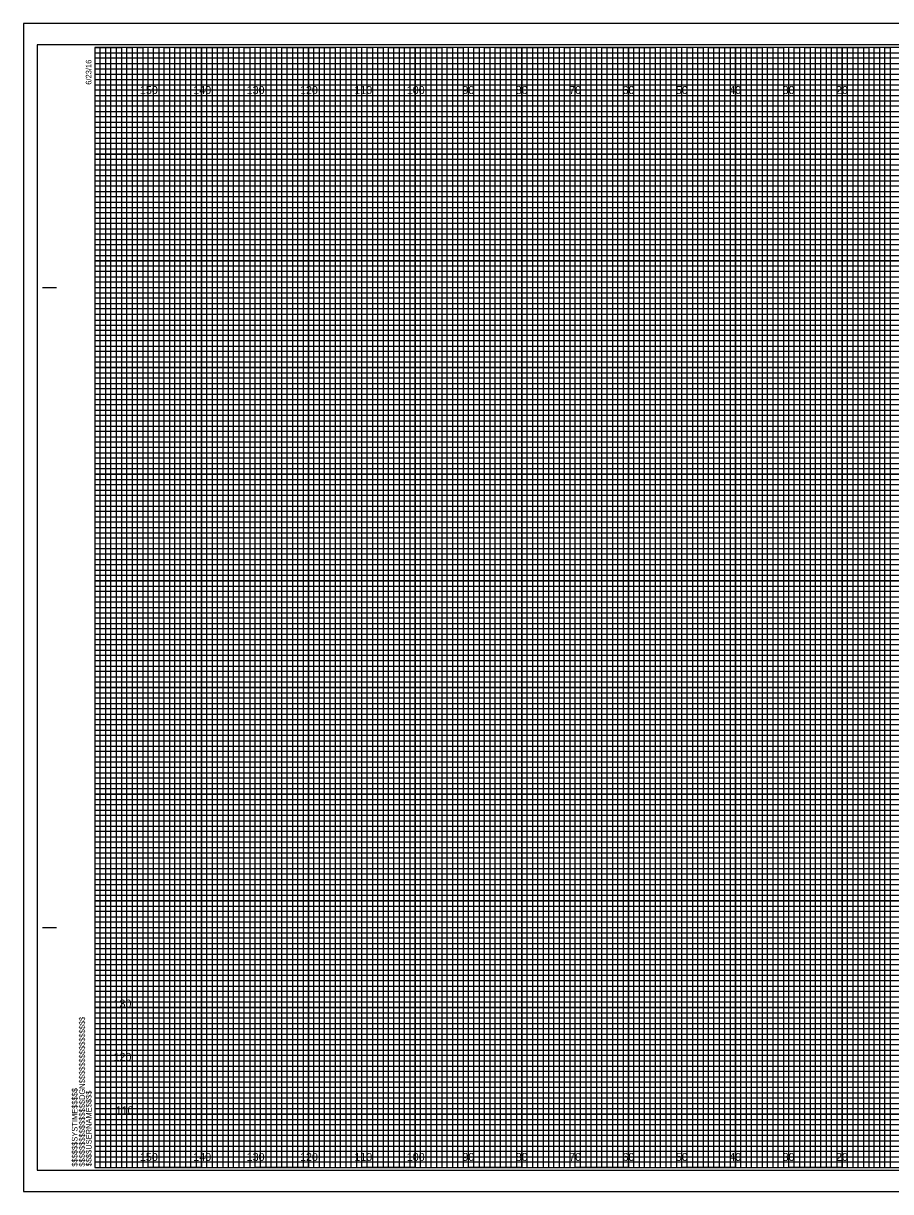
# Model space of a CAD drawing. Extents: x -13 to 323, y -5 to 434.
# Drawn here: x -13.4 to 149.1, y 215.5 to 434.5 of the extents above; entities that cross this region are included whole.
import ezdxf

# ---------------------------------------------------------------- set-up
doc = ezdxf.new("R2010")
doc.units = 0
for name, color, linetype in [('Exist CMT Pavement', 7, 'Continuous'), ('Exist Cross Section Cell', 7, 'Continuous'), ('Exist XS Center Line Elevation Label', 7, 'Continuous'), ('Exist XS Ground Line', 7, 'Continuous'), ('Prop CMT Concrete Structures', 7, 'Continuous'), ('Prop CMT Pvmt Course 1 Wedge', 7, 'Continuous'), ('Prop CMT Pvmt Course 2', 7, 'Continuous'), ('Prop CMT Pvmt Course 2 Wedge', 7, 'Continuous'), ('Prop CMT Pvmt Course 3', 7, 'Continuous'), ('Prop CMT Pvmt Course 3 Wedge', 7, 'Continuous'), ('Scratch_Level_0', 7, 'Continuous')]:
    doc.layers.add(name, color=color, linetype=linetype)

msp = doc.modelspace()

# ---------------------------------------------------------------- linework, layer by layer
at = {"layer": 'Exist XS Center Line Elevation Label'}
for points in [[(0, 430), (5, 430), (5, 220), (15, 220), (15, 430), (25, 430), (25, 220), (35, 220), (35, 430), (45, 430), (45, 220), (55, 220), (55, 430), (65, 430), (65, 220), (75, 220), (75, 430), (85, 430), (85, 220), (95, 220), (95, 430), (105, 430), (105, 220), (115, 220), (115, 430), (125, 430), (125, 220), (135, 220), (135, 430), (145, 430), (145, 220), (155, 220)], [(0, 425), (275, 425)], [(0, 405), (320, 405), (320, 415), (0, 415)], [(0, 385), (320, 385), (320, 395), (0, 395)], [(0, 365), (320, 365), (320, 375), (0, 375)], [(0, 345), (320, 345), (320, 355), (0, 355)], [(0, 325), (320, 325), (320, 335), (0, 335)], [(0, 305), (320, 305), (320, 315), (0, 315)], [(0, 285), (320, 285), (320, 295), (0, 295)], [(0, 265), (320, 265), (320, 275), (0, 275)], [(0, 245), (320, 245), (320, 255), (0, 255)], [(0, 225), (320, 225), (320, 235), (0, 235)]]:
    msp.add_lwpolyline(points, dxfattribs=at)
at = {"layer": 'Exist XS Ground Line'}
for p, q in [((10, 430), (0, 430)), ((10, 220), (10, 430)), ((30, 430), (20, 430)), ((20, 430), (20, 220)), ((30, 220), (30, 430)), ((50, 430), (40, 430)), ((40, 430), (40, 220)), ((50, 220), (50, 430)), ((70, 430), (60, 430)), ((60, 430), (60, 220)), ((70, 220), (70, 430)), ((90, 430), (80, 430)), ((80, 430), (80, 220)), ((90, 220), (90, 430)), ((110, 430), (100, 430)), ((100, 430), (100, 220)), ((110, 220), (110, 430)), ((130, 430), (120, 430)), ((120, 430), (120, 220)), ((130, 220), (130, 430)), ((150, 430), (140, 430)), ((140, 430), (140, 220)), ((20, 220), (10, 220)), ((40, 220), (30, 220)), ((60, 220), (50, 220)), ((80, 220), (70, 220)), ((100, 220), (90, 220)), ((120, 220), (110, 220)), ((140, 220), (130, 220))]:
    msp.add_line(p, q, dxfattribs=at)
for points in [[(0, 420), (320, 420), (320, 410), (0, 410)], [(0, 400), (320, 400), (320, 390), (0, 390)], [(0, 380), (320, 380), (320, 370), (0, 370)], [(0, 360), (320, 360), (320, 350), (0, 350)], [(0, 340), (320, 340), (320, 330), (0, 330)], [(0, 320), (320, 320), (320, 310), (0, 310)], [(0, 300), (320, 300), (320, 290), (0, 290)], [(0, 280), (320, 280), (320, 270), (0, 270)], [(0, 260), (320, 260), (320, 250), (0, 250)], [(0, 240), (320, 240), (320, 230), (0, 230)]]:
    msp.add_lwpolyline(points, dxfattribs=at)
at = {"layer": 'Prop CMT Concrete Structures'}
for p, q in [((323.3, 434.5), (-13.4, 434.5)), ((-13.4, 434.5), (-13.4, 215.5)), ((-13.4, 215.5), (323.3, 215.5))]:
    msp.add_line(p, q, dxfattribs=at)
at = {"layer": 'Prop CMT Pvmt Course 1 Wedge'}
msp.add_lwpolyline([(-13.4, 215.5), (323.3, 215.5), (323.3, 434.5), (-13.4, 434.5)], close=True, dxfattribs=at)
at = {"layer": 'Prop CMT Pvmt Course 2'}
for p, q in [((-9.8, 385), (-7.3, 385)), ((-9.7, 385), (-7.2, 385)), ((-9.8, 265), (-7.3, 265)), ((-9.7, 265), (-7.2, 265)), ((0, 220), (0, 220)), ((0, 220), (0, 220)), ((0, 220), (0, 220)), ((0, 220), (0, 220)), ((0, 220), (0, 220)), ((0, 220), (0, 220)), ((0, 220), (0, 220))]:
    msp.add_line(p, q, dxfattribs=at)
msp.add_lwpolyline([(320, 430), (0, 430), (0, 220), (320, 220)], close=True, dxfattribs=at)
at = {"layer": 'Prop CMT Pvmt Course 2 Wedge'}
msp.add_lwpolyline([(-10.8, 219.5), (322.4, 219.5), (322.4, 430.5), (-10.8, 430.5)], close=True, dxfattribs=at)
at = {"layer": 'Prop CMT Pvmt Course 3'}
for points in [[(0, 220), (1, 220), (1, 430), (2, 430), (2, 220)], [(2, 220), (3, 220), (3, 430), (4, 430), (4, 220)], [(5, 220), (6, 220), (6, 430), (7, 430), (7, 220)], [(7, 220), (8, 220), (8, 430), (9, 430), (9, 220)], [(10, 220), (11, 220), (11, 430), (12, 430), (12, 220)], [(12, 220), (13, 220), (13, 430), (14, 430), (14, 220)], [(15, 220), (16, 220), (16, 430), (17, 430), (17, 220)], [(17, 220), (18, 220), (18, 430), (19, 430), (19, 220)], [(20, 220), (21, 220), (21, 430), (22, 430), (22, 220)], [(22, 220), (23, 220), (23, 430), (24, 430), (24, 220)], [(25, 220), (26, 220), (26, 430), (27, 430), (27, 220)], [(27, 220), (28, 220), (28, 430), (29, 430), (29, 220)], [(30, 220), (31, 220), (31, 430), (32, 430), (32, 220)], [(32, 220), (33, 220), (33, 430), (34, 430), (34, 220)], [(35, 220), (36, 220), (36, 430), (37, 430), (37, 220)], [(37, 220), (38, 220), (38, 430), (39, 430), (39, 220)], [(40, 220), (41, 220), (41, 430), (42, 430), (42, 220)], [(42, 220), (43, 220), (43, 430), (44, 430), (44, 220)], [(45, 220), (46, 220), (46, 430), (47, 430), (47, 220)], [(47, 220), (48, 220), (48, 430), (49, 430), (49, 220)], [(50, 220), (51, 220), (51, 430), (52, 430), (52, 220)], [(52, 220), (53, 220), (53, 430), (54, 430), (54, 220)], [(55, 220), (56, 220), (56, 430), (57, 430), (57, 220)], [(57, 220), (58, 220), (58, 430), (59, 430), (59, 220)], [(60, 220), (61, 220), (61, 430), (62, 430), (62, 220)], [(62, 220), (63, 220), (63, 430), (64, 430), (64, 220)], [(65, 220), (66, 220), (66, 430), (67, 430), (67, 220)], [(67, 220), (68, 220), (68, 430), (69, 430), (69, 220)], [(70, 220), (71, 220), (71, 430), (72, 430), (72, 220)], [(72, 220), (73, 220), (73, 430), (74, 430), (74, 220)], [(75, 220), (76, 220), (76, 430), (77, 430), (77, 220)], [(77, 220), (78, 220), (78, 430), (79, 430), (79, 220)], [(80, 220), (81, 220), (81, 430), (82, 430), (82, 220)], [(82, 220), (83, 220), (83, 430), (84, 430), (84, 220)], [(85, 220), (86, 220), (86, 430), (87, 430), (87, 220)], [(87, 220), (88, 220), (88, 430), (89, 430), (89, 220)], [(90, 220), (91, 220), (91, 430), (92, 430), (92, 220)], [(92, 220), (93, 220), (93, 430), (94, 430), (94, 220)], [(95, 220), (96, 220), (96, 430), (97, 430), (97, 220)], [(97, 220), (98, 220), (98, 430), (99, 430), (99, 220)], [(100, 220), (101, 220), (101, 430), (102, 430), (102, 220)], [(102, 220), (103, 220), (103, 430), (104, 430), (104, 220)], [(105, 220), (106, 220), (106, 430), (107, 430), (107, 220)], [(107, 220), (108, 220), (108, 430), (109, 430), (109, 220)], [(110, 220), (111, 220), (111, 430), (112, 430), (112, 220)], [(112, 220), (113, 220), (113, 430), (114, 430), (114, 220)], [(115, 220), (116, 220), (116, 430), (117, 430), (117, 220)], [(117, 220), (118, 220), (118, 430), (119, 430), (119, 220)], [(120, 220), (121, 220), (121, 430), (122, 430), (122, 220)], [(122, 220), (123, 220), (123, 430), (124, 430), (124, 220)], [(125, 220), (126, 220), (126, 430), (127, 430), (127, 220)], [(127, 220), (128, 220), (128, 430), (129, 430), (129, 220)], [(130, 220), (131, 220), (131, 430), (132, 430), (132, 220)], [(132, 220), (133, 220), (133, 430), (134, 430), (134, 220)], [(135, 220), (136, 220), (136, 430), (137, 430), (137, 220)], [(137, 220), (138, 220), (138, 430), (139, 430), (139, 220)], [(140, 220), (141, 220), (141, 430), (142, 430), (142, 220)], [(142, 220), (143, 220), (143, 430), (144, 430), (144, 220)], [(145, 220), (146, 220), (146, 430), (147, 430), (147, 220)], [(147, 220), (148, 220), (148, 430), (149, 430), (149, 220)]]:
    msp.add_lwpolyline(points, dxfattribs=at)
at = {"layer": 'Prop CMT Pvmt Course 3 Wedge'}
for p, q in [((10, 220), (10, 430)), ((20, 220), (20, 430)), ((30, 220), (30, 430)), ((40, 220), (40, 430)), ((50, 220), (50, 430)), ((60, 220), (60, 430)), ((70, 220), (70, 430)), ((80, 220), (80, 430)), ((90, 220), (90, 430)), ((100, 220), (100, 430)), ((110, 220), (110, 430)), ((120, 220), (120, 430)), ((130, 220), (130, 430)), ((140, 220), (140, 430)), ((0, 420), (320, 420)), ((0, 410), (320, 410)), ((0, 400), (320, 400)), ((0, 390), (320, 390)), ((0, 380), (320, 380)), ((0, 370), (320, 370)), ((0, 360), (320, 360)), ((0, 350), (320, 350)), ((0, 340), (320, 340)), ((0, 330), (320, 330)), ((0, 320), (320, 320)), ((0, 310), (320, 310)), ((0, 300), (320, 300)), ((0, 290), (320, 290)), ((0, 280), (320, 280)), ((0, 270), (320, 270)), ((0, 260), (320, 260)), ((0, 250), (320, 250)), ((0, 240), (320, 240)), ((0, 230), (320, 230))]:
    msp.add_line(p, q, dxfattribs=at)
at = {"layer": 'Scratch_Level_0'}
for p, q in [((0, 429), (260, 429)), ((260, 427.98), (0, 427.98)), ((0, 427.98), (0, 427)), ((0, 427), (260, 427)), ((260, 425.89), (0, 425.89)), ((0, 425.89), (0, 424)), ((0, 424), (320, 424))]:
    msp.add_line(p, q, dxfattribs=at)
for points in [[(0, 423), (270, 423), (320, 423), (320, 422), (0, 422)], [(0, 421), (320, 421), (320, 419), (0, 419)], [(0, 418), (320, 418), (320, 417), (0, 416.98)], [(0, 416), (320, 416), (320, 414), (0, 414)], [(0, 413), (320, 413), (320, 412), (0, 412)], [(0, 411), (320, 411), (320, 409), (0, 409)], [(0, 408), (320, 408), (320, 407), (0, 407)], [(0, 406), (320, 406), (320, 404), (0, 404)], [(0, 403), (320, 403), (320, 402), (0, 402)], [(0, 401), (320, 401), (320, 399), (0, 399)], [(0, 398), (320, 398), (320, 397), (0, 397)], [(0, 396), (320, 396), (320, 393.95), (320, 393), (320, 392), (0, 392)], [(0, 394), (320, 394), (320, 393), (0, 393)], [(0, 391), (320, 391), (320, 389), (0, 389.03)], [(0, 389.03), (320, 389), (320, 388), (0, 388)], [(0, 387), (320, 387), (320, 386), (0, 386)], [(0, 384), (320, 384), (320, 383), (0, 383)], [(0, 382), (320, 382), (320, 381), (0, 381)], [(-0.07, 378.89), (320, 378.89), (320, 377.88), (-0.07, 377.88)], [(0, 377), (320, 377), (320, 376), (0, 376)], [(0, 374), (320, 374), (320, 373), (0, 373)], [(0, 372), (320, 372), (320, 371), (0, 371)], [(0, 369), (320, 369), (320, 368), (0, 368)], [(0, 367), (320, 367), (320, 366), (0, 366)], [(0, 364), (320, 364), (320, 363), (0, 363)], [(0, 362), (320, 362), (320, 361), (0, 361)], [(0, 359), (320, 359), (319.99, 357.98), (0, 358)], [(0, 357), (320, 357), (320, 356), (0, 356)], [(0, 354), (320, 354), (320, 353), (0, 353)], [(0, 352), (320, 352), (320, 351), (0, 351)], [(0, 349), (320, 349), (320, 348), (0, 348)], [(0, 347), (320, 347), (320, 346), (0, 346)], [(0, 344), (320, 344), (320, 343), (0, 343)], [(0, 342), (320, 342), (320, 341), (0, 341)], [(0, 339), (320, 339), (320, 338), (0, 338)], [(0, 336.99), (320.07, 336.91), (320, 336), (0, 336)], [(0, 334), (320, 334), (320, 333), (0, 333)], [(0, 332), (320, 332), (320, 331), (0, 331)], [(0, 329), (320, 329), (320, 328), (0, 328)], [(0, 327), (320, 327), (320, 326), (0, 326)], [(0, 324), (320, 324), (320, 323), (0, 323)], [(0, 322), (320, 322), (320, 321), (0, 321)], [(0, 319), (320, 319), (320, 318), (0, 318)], [(0, 317), (320, 317), (320, 316), (0, 316)], [(0, 314), (320, 314), (320, 313), (0, 313)], [(0, 312), (320, 312), (320, 311), (0, 311)], [(0, 309), (320, 309), (320, 308), (0, 308)], [(0, 307), (320, 307), (320, 306), (0, 306)], [(0, 304), (320, 304), (320, 303), (0, 303)], [(0, 302), (320, 302), (320, 301), (0, 301)], [(0, 299), (320, 299), (319.99, 297.98), (0, 298)], [(0, 297), (320, 297), (320, 296), (0, 296)], [(0, 294), (320, 294), (320, 293), (0, 293)], [(0, 292), (320, 292), (320, 291), (0, 291)], [(0, 289), (320, 289), (320, 288), (0, 288)], [(0, 287), (320, 287), (320, 286), (0, 286)], [(0, 284), (320, 284), (320, 283), (0, 283)], [(0, 282), (320, 282), (320, 281), (0, 281)], [(0, 279), (320, 279), (320, 278), (0, 278)], [(0, 276.99), (320.07, 276.91), (320, 276), (0, 276)], [(0, 274), (320, 274), (320, 273), (0, 273)], [(0, 272), (320, 272), (320, 271), (0, 271)], [(0, 269), (320, 269), (320, 268), (0, 268)], [(0, 267), (320, 267), (320, 266), (0, 266)], [(0, 264), (320, 264), (320, 263), (0, 263)], [(0, 262), (320, 262), (320, 261), (0, 261)], [(0, 259), (320, 259), (320, 258), (0, 258)], [(0, 257), (320, 257), (320, 256), (0, 256)], [(0, 254), (320, 254), (320, 253), (0, 253)], [(0, 252), (320, 252), (320, 251), (0, 251)], [(0, 249), (320, 249), (320, 248), (0, 248)], [(0, 247), (320, 247), (320, 246), (0, 246)], [(0, 244), (320, 244), (320, 243), (0, 243)], [(0, 242), (320, 242), (320, 241), (0, 241)], [(0, 239), (320, 239), (320, 238), (0, 238)], [(0, 237), (320, 237), (320, 236), (0, 236)], [(0, 234), (320, 234), (320, 233), (0, 233)], [(0, 232), (320, 232), (320, 231), (0, 231)], [(0, 229), (320, 229), (320, 228), (0, 228)], [(0, 227), (320, 227), (320, 226), (0, 226)], [(0, 224), (320, 224), (320, 223), (0, 223)], [(0, 222), (320, 222), (320, 221), (0, 221)]]:
    msp.add_lwpolyline(points, dxfattribs=at)

# ---------------------------------------------------------------- texts
at = {"layer": 'Exist CMT Pavement'}
for s, p in [('130', (3.49, 250)), ('120', (3.5, 240)), ('110', (3.88, 230))]:
    msp.add_text(s, height=1.5, dxfattribs=at).set_placement(p)
at = {"layer": 'Exist Cross Section Cell'}
for s, p in [('150', (8.44, 421.25)), ('140', (18.44, 421.25)), ('130', (28.44, 421.25)), ('120', (38.44, 421.25)), ('110', (48.62, 421.25)), ('100', (58.44, 421.25)), ('90', (68.86, 421.25)), ('80', (78.86, 421.25)), ('70', (88.86, 421.25)), ('60', (98.86, 421.25)), ('50', (108.86, 421.25)), ('40', (118.86, 421.25)), ('30', (128.86, 421.25)), ('20', (138.86, 421.25)), ('150', (8.44, 221.25)), ('140', (18.44, 221.25)), ('130', (28.44, 221.25)), ('120', (38.44, 221.25)), ('110', (48.62, 221.25)), ('100', (58.44, 221.25)), ('90', (68.86, 221.25)), ('80', (78.86, 221.25)), ('70', (88.86, 221.25)), ('60', (98.86, 221.25)), ('50', (108.86, 221.25)), ('40', (118.86, 221.25)), ('30', (128.86, 221.25)), ('20', (138.86, 221.25))]:
    msp.add_text(s, height=1.5, dxfattribs=at).set_placement(p)
at = {"layer": 'Prop CMT Pvmt Course 2'}
for s, p in [('6/23/16', (-0.65, 423)), ('$$$$$$$$$$$$$$$$DGN$$$$$$$$$$$$$$$$', (-1.88, 220.18)), ('$$$$$$SYSTIME$$$$$', (-3.26, 220.18)), ('$$$$USERNAME$$$$', (-0.62, 220.23))]:
    msp.add_text(s, height=1.05, rotation=90, dxfattribs=at).set_placement(p)

doc.saveas('drawing.dxf')
